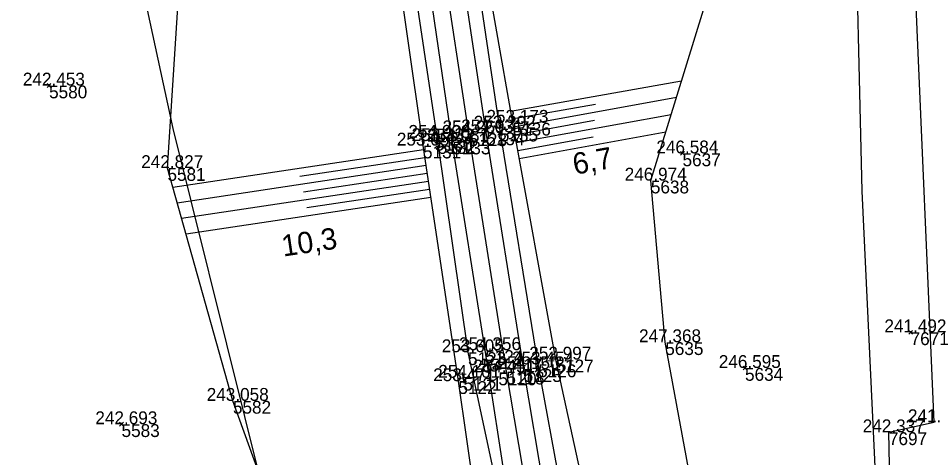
# Model space of a CAD drawing. Extents: x -809970 to -809480, y -1011362 to -1010672.
# Drawn here: x -809898.5 to -809812.8, y -1010932.6 to -1010891.5 of the extents above; entities that cross this region are included whole.
import ezdxf

# ---------------------------------------------------------------- set-up
doc = ezdxf.new("R2010")
doc.units = 0
for name, color, linetype in [('Vrstva 1', 7, 'Continuous'), ('Vrstva 17', 7, 'Continuous'), ('Vrstva 4', 7, 'Continuous'), ('Vrstva 48', 7, 'Continuous'), ('Vrstva 49', 7, 'Continuous'), ('Vrstva 53', 7, 'Continuous'), ('Vrstva 60', 7, 'Continuous'), ('Vrstva 61', 7, 'Continuous'), ('Vrstva 7', 7, 'Continuous')]:
    doc.layers.add(name, color=color, linetype=linetype)

msp = doc.modelspace()

# ---------------------------------------------------------------- linework, layer by layer
at = {"layer": 'Vrstva 1'}
msp.add_lwpolyline([(-809820.002, -1011038.37), (-809825.442, -1011026.104), (-809830.785, -1011012.658), (-809834.485, -1011002.308), (-809836.415, -1010996.462), (-809838.541, -1010989.632), (-809841.189, -1010980.417), (-809842.723, -1010974.633), (-809843.612, -1010971.08), (-809845.723, -1010962.088), (-809847.264, -1010954.929), (-809848.141, -1010950.637), (-809848.896, -1010946.737), (-809850.898, -1010935.751), (-809852.809, -1010924.513), (-809856.326, -1010902.237), (-809858.786, -1010885.982), (-809860.306, -1010875.864), (-809863.238, -1010856.222), (-809865.824, -1010838.832), (-809869.271, -1010815.693)], dxfattribs=at)
at = {"layer": 'Vrstva 17'}
msp.add_lwpolyline([(-809816.368, -1010956.508), (-809815.855, -1010953.161), (-809816.885, -1010937.943), (-809817.019, -1010930.187), (-809812.79, -1010929.244), (-809814.558, -1010888.198), (-809811.641, -1010871.97), (-809791.356, -1010869.614)], dxfattribs=at)
at = {"layer": 'Vrstva 4'}
for points in [[(-809821.494, -1011039.157), (-809826.205, -1011028.819), (-809833.001, -1011011.481), (-809837.78, -1010997.54), (-809838.806, -1010997.207), (-809843.283, -1010980.934), (-809843.041, -1010980.213), (-809846.285, -1010966.658), (-809849.289, -1010953.139), (-809852.706, -1010936.051), (-809854.789, -1010922.512), (-809857.871, -1010903.005), (-809861.561, -1010877.867), (-809862.279, -1010876.008), (-809867.764, -1010839.12), (-809867.776, -1010837.677), (-809868.98, -1010830.232), (-809873.561, -1010797.792), (-809876.118, -1010779.988), (-809878.6, -1010761.673), (-809881.093, -1010740.742), (-809883.606, -1010712.064)], [(-809818.366, -1011037.45), (-809824.503, -1011023.859), (-809827.98, -1011014.861), (-809832.548, -1011002.245), (-809834.342, -1010996.578), (-809834.105, -1010995.845), (-809838.678, -1010979.669), (-809839.533, -1010979.34), (-809840.375, -1010976.742), (-809844.107, -1010961.611), (-809846.272, -1010950.024), (-809849.263, -1010935.563), (-809851.188, -1010924.288), (-809854.685, -1010902.149), (-809857.441, -1010883.897), (-809858.703, -1010875.93), (-809858.211, -1010875.546), (-809863.759, -1010838.589), (-809864.243, -1010838.113), (-809864.684, -1010833.803), (-809870.275, -1010797.222)], [(-809838.678, -1010979.669), (-809838.423, -1010979.516), (-809837.883, -1010979.54), (-809837.013, -1010979.451), (-809837.103, -1010978.997), (-809837.176, -1010978.22), (-809837.88, -1010976.841), (-809838.297, -1010976.333), (-809838.847, -1010973.75), (-809841.894, -1010960.179), (-809844.644, -1010949.504), (-809847.686, -1010935.566), (-809849.835, -1010923.843), (-809853.415, -1010901.801), (-809856.171, -1010883.326), (-809856.72, -1010879.277), (-809857.134, -1010878.975), (-809857.359, -1010879.02), (-809857.838, -1010876.123), (-809858.079, -1010875.541), (-809858.211, -1010875.546)], [(-809843.283, -1010980.934), (-809843.235, -1010980.877), (-809844.412, -1010980.573), (-809845.115, -1010978.271), (-809845.085, -1010978.25), (-809845.209, -1010978.233), (-809846.601, -1010972.791), (-809850.517, -1010953.058), (-809853.547, -1010935.954), (-809856.396, -1010922.703), (-809859.23, -1010902.96), (-809862.455, -1010881.274), (-809862.589, -1010879.865), (-809862.252, -1010879.786), (-809862, -1010879.706), (-809862.476, -1010876.825), (-809862.419, -1010876.062), (-809862.279, -1010876.008)]]:
    msp.add_lwpolyline(points, dxfattribs=at)
at = {"layer": 'Vrstva 48'}
for p, q in [((-809852.416, -1010900.153), (-809836.416, -1010897.324)), ((-809852.285, -1010900.892), (-809844.475, -1010899.511)), ((-809852.153, -1010901.63), (-809836.891, -1010898.867)), ((-809851.886, -1010903.106), (-809837.389, -1010900.482)), ((-809852.02, -1010902.368), (-809844.58, -1010901.021)), ((-809851.619, -1010904.582), (-809837.886, -1010902.096)), ((-809851.752, -1010903.844), (-809844.695, -1010902.566)), ((-809860.548, -1010903.776), (-809884.007, -1010907.3)), ((-809860.436, -1010904.517), (-809872.119, -1010906.272)), ((-809860.325, -1010905.259), (-809883.597, -1010908.755)), ((-809860.213, -1010906.001), (-809871.803, -1010907.742)), ((-809860.102, -1010906.742), (-809883.188, -1010910.21)), ((-809859.991, -1010907.484), (-809871.487, -1010909.211)), ((-809859.879, -1010908.226), (-809882.778, -1010911.666))]:
    msp.add_line(p, q, dxfattribs=at)
at = {"layer": 'Vrstva 49'}
for p, q in [((-809895.768, -1010897.591), (-809895.414, -1010897.945)), ((-809895.768, -1010897.945), (-809895.414, -1010897.591)), ((-809836.505, -1010903.939), (-809836.151, -1010904.293)), ((-809836.505, -1010904.293), (-809836.151, -1010903.939)), ((-809815.17, -1010920.661), (-809814.816, -1010921.015)), ((-809815.17, -1010921.015), (-809814.816, -1010920.661)), ((-809830.659, -1010923.999), (-809830.305, -1010924.353)), ((-809830.659, -1010924.353), (-809830.305, -1010923.999)), ((-809888.988, -1010929.255), (-809888.634, -1010929.609)), ((-809888.988, -1010929.609), (-809888.634, -1010929.255))]:
    msp.add_line(p, q, dxfattribs=at)
for points in [[(-809856.883, -1010875.823), (-809855.422, -1010883.15), (-809852.222, -1010901.25), (-809848.214, -1010923.392), (-809845.696, -1010934.941), (-809844.027, -1010949.48), (-809841.894, -1010960.179), (-809838.847, -1010973.75), (-809838.297, -1010976.333), (-809838.163, -1010976.258), (-809836.936, -1010979.029), (-809837.013, -1010979.451), (-809825.985, -1010977.935), (-809824.923, -1010977.248)], [(-809824.923, -1010977.248), (-809832.146, -1010953.133), (-809837.944, -1010921.765), (-809839.29, -1010906.656), (-809832.688, -1010885.218), (-809835.079, -1010880.738), (-809839.978, -1010876.967), (-809844.518, -1010876.01), (-809844.618, -1010877), (-809856.883, -1010875.823)], [(-809846.733, -1010986.717), (-809852.633, -1010985.242), (-809855.833, -1010983.597), (-809858.12, -1010981.877), (-809860.248, -1010978.081), (-809864.337, -1010968.616), (-809864.72, -1010965.088), (-809878.39, -1010927.249), (-809884.518, -1010905.485), (-809883.3, -1010886.554), (-809883.077, -1010886.562), (-809880.73, -1010884.265), (-809876.323, -1010881.843), (-809865.405, -1010877.268)], [(-809844.216, -1010981.17), (-809845.209, -1010978.233), (-809845.714, -1010977.964), (-809847.365, -1010972.779), (-809851.193, -1010953.154), (-809855.722, -1010936.261), (-809857.298, -1010925.409), (-809860.607, -1010903.381), (-809863.59, -1010882.451), (-809864.222, -1010876.871), (-809865.405, -1010877.268)]]:
    msp.add_lwpolyline(points, dxfattribs=at)
at = {"layer": 'Vrstva 53'}
for points in [[(-809810.89, -1011076.81), (-809836.26, -1011028.53), (-809850.32, -1011003.33), (-809854.51, -1011000.24), (-809856.34, -1010998.68), (-809859.52, -1010995.97), (-809864.77, -1010992.44), (-809865.72, -1010986.44), (-809870.58, -1010955.65), (-809883.99, -1010901.78), (-809890.33, -1010872.36), (-809892.39, -1010868.68), (-809893.92, -1010865.41), (-809894.78, -1010861.65), (-809898.21, -1010828.41), (-809898.47, -1010814.6), (-809887.66, -1010796.86), (-809893.8, -1010725.05), (-809890.92, -1010677.02)], [(-809848.47, -1010824.63), (-809848.99, -1010834.52), (-809828.94, -1010831.94), (-809811.76, -1010846.11), (-809806.99, -1010849.89), (-809798.33, -1010856.76), (-809803.49, -1010861.61), (-809820.27, -1010877.38), (-809819.54, -1010907.65), (-809817.34, -1010954.54), (-809819.55, -1010971.19), (-809826.87, -1010981.55), (-809825.08, -1010988.69), (-809823.59, -1010994.66), (-809817.83, -1011024.91), (-809805.06, -1011048.21)]]:
    msp.add_lwpolyline(points, dxfattribs=at)
at = {"layer": 'Vrstva 60'}
for p, q in [((-809895.591, -1010897.768), (-809895.591, -1010897.768)), ((-809852.222, -1010901.25), (-809852.222, -1010901.25)), ((-809854.685, -1010902.149), (-809854.685, -1010902.149)), ((-809853.415, -1010901.801), (-809853.415, -1010901.801)), ((-809859.517, -1010902.658), (-809859.517, -1010902.658)), ((-809859.23, -1010902.96), (-809859.23, -1010902.96)), ((-809857.871, -1010903.005), (-809857.871, -1010903.005)), ((-809856.326, -1010902.237), (-809856.326, -1010902.237)), ((-809860.607, -1010903.381), (-809860.607, -1010903.381)), ((-809836.328, -1010904.116), (-809836.328, -1010904.116)), ((-809884.518, -1010905.485), (-809884.518, -1010905.485)), ((-809839.29, -1010906.656), (-809839.29, -1010906.656)), ((-809814.993, -1010920.838), (-809814.993, -1010920.838)), ((-809837.944, -1010921.765), (-809837.944, -1010921.765)), ((-809856.396, -1010922.703), (-809856.396, -1010922.703)), ((-809854.789, -1010922.512), (-809854.789, -1010922.512)), ((-809848.214, -1010923.392), (-809848.214, -1010923.392)), ((-809851.188, -1010924.288), (-809851.188, -1010924.288)), ((-809849.835, -1010923.843), (-809849.835, -1010923.843)), ((-809830.482, -1010924.176), (-809830.482, -1010924.176)), ((-809856.825, -1010925.089), (-809856.825, -1010925.089)), ((-809853.553, -1010924.597), (-809853.553, -1010924.597)), ((-809852.809, -1010924.513), (-809852.809, -1010924.513)), ((-809857.298, -1010925.409), (-809857.298, -1010925.409)), ((-809878.39, -1010927.249), (-809878.39, -1010927.249)), ((-809888.811, -1010929.432), (-809888.811, -1010929.432)), ((-809817.019, -1010930.187), (-809817.019, -1010930.187))]:
    msp.add_line(p, q, dxfattribs=at)
at = {"layer": 'Vrstva 7'}
for p, q in [((-809859.442, -1010903.152), (-809859.592, -1010902.164)), ((-809860.011, -1010902.733), (-809859.023, -1010902.583)), ((-809857.319, -1010925.167), (-809856.331, -1010925.011)), ((-809856.747, -1010925.583), (-809856.903, -1010924.595))]:
    msp.add_line(p, q, dxfattribs=at)

# ---------------------------------------------------------------- texts
at = {"layer": 'Vrstva 48'}
for s, rotation, p in [('6,7', 10.26021, (-809846.41, -1010906.12)), ('10,3', 8.54298, (-809873.683, -1010913.767))]:
    msp.add_text(s, height=2, rotation=rotation, dxfattribs=at).set_placement(p)
at = {"layer": 'Vrstva 60'}
for s, p in [('5580', (-809895.591, -1010898.968)), ('5136', (-809852.222, -1010902.45)), ('5134', (-809854.685, -1010903.349)), ('5135', (-809853.415, -1010903.001)), ('5130', (-809859.517, -1010903.858)), ('5132', (-809859.23, -1010904.16)), ('5133', (-809857.871, -1010904.205)), ('5128', (-809856.326, -1010903.437)), ('5131', (-809860.607, -1010904.581)), ('5637', (-809836.328, -1010905.316)), ('5581', (-809884.518, -1010906.685)), ('5638', (-809839.29, -1010907.856)), ('7671', (-809814.993, -1010922.038)), ('5635', (-809837.944, -1010922.965)), ('5123', (-809856.396, -1010923.903)), ('5124', (-809854.789, -1010923.712)), ('5127', (-809848.214, -1010924.592)), ('5125', (-809851.188, -1010925.488)), ('5126', (-809849.835, -1010925.043)), ('5634', (-809830.482, -1010925.376)), ('5121', (-809856.825, -1010926.289)), ('5120', (-809853.553, -1010925.797)), ('5118', (-809852.809, -1010925.713)), ('5122', (-809857.298, -1010926.609)), ('5582', (-809878.39, -1010928.449)), ('5583', (-809888.811, -1010930.632)), ('7697', (-809817.019, -1010931.387))]:
    msp.add_text(s, height=1.2, dxfattribs=at).set_placement(p)
at = {"layer": 'Vrstva 61'}
for s, p in [('242.453', (-809898.043, -1010897.768)), ('253.173', (-809854.674, -1010901.25)), ('254.269', (-809858.78, -1010902.237)), ('254.031', (-809857.042, -1010902.149)), ('253.292', (-809855.863, -1010901.801)), ('253.052', (-809863.055, -1010903.381)), ('254.008', (-809861.971, -1010902.658)), ('253.333', (-809861.682, -1010902.96)), ('254.081', (-809860.228, -1010903.005)), ('246.584', (-809838.779, -1010904.116)), ('242.827', (-809886.97, -1010905.485)), ('246.974', (-809841.741, -1010906.656)), ('241.492', (-809817.441, -1010920.838)), ('247.368', (-809840.398, -1010921.765)), ('253.605', (-809858.852, -1010922.703)), ('254.356', (-809857.241, -1010922.512)), ('253.454', (-809852.286, -1010923.843)), ('252.997', (-809850.666, -1010923.392)), ('254.451', (-809855.91, -1010924.597)), ('254.417', (-809855.261, -1010924.513)), ('254.150', (-809853.639, -1010924.288)), ('246.595', (-809832.938, -1010924.176)), ('253.471', (-809859.655, -1010925.409)), ('254.101', (-809859.182, -1010925.089)), ('243.058', (-809880.844, -1010927.249)), ('242.693', (-809891.263, -1010929.432)), ('241.863', (-809815.242, -1010929.244)), ('242.337', (-809819.471, -1010930.187))]:
    msp.add_text(s, height=1.2, dxfattribs=at).set_placement(p)

doc.saveas('drawing.dxf')
